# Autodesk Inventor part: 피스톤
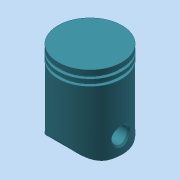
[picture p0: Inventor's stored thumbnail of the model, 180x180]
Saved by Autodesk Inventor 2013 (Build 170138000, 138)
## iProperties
Created: 2017-05
Part Number: 피스톤
Material: 알루미늄 6061
Document SubType Name: Modeling
Designer: mduedu
Density: 2.71 g/cm^3
Mass: 87.6982 g
Surface Area: 150.47 cm^2
Volume: 32.361 cm^3
Author: mduedu
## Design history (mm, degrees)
sketch "스케치1"
  geometry: L1 (0, 0)-(20, 0); L2 (20, -50)-(15, -50); L3 (15, -50)-(15, -5); L4 (15, -5)-(0, -5); L5 (0, -5)-(0, 0); L6 (20, -3)-(18, -3); L7 (18, -3)-(18, -5); L8 (18, -5)-(20, -5); L9 (20, -7)-(18, -7); L10 (18, -7)-(18, -9); L11 (18, -9)-(20, -9); L12 (20, 0)-(20, -3); L13 (20, -5)-(20, -7); L14 (20, -9)-(20, -50); L15 (0, -60)-(0, 10) reference
  constraints: 28 end point, 10 parallel, 5 perpendicular, 4 collinear, 3 horizontal
  dimensions: "d0" = 20 distance of L1.start L1.end; "d1" = 2 distance of L6.start L6.end; "d2" = 2 distance of L6.end L7.end; "d3" = 2 distance of L8.end L9.start; "d4" = 3 distance of L1.end L6.start; "d5" = 5 distance of L2.start L2.end; "d6" = 50 distance between parallel lines of L1 L2; "d7" = 5 distance of L4.end L1.start
revolve "회전1" sketch "스케치1" stored, may be unused: angle "d8" = 90 deg
fillet "모깎기1" dims "d9" = 1
sketch "스케치2"
  geometry: L1 (-50, 15)-(-50, -15) reference; C1 r 10 at (-40, 0); 1 further point
  constraints: 1 centre point, 1 horizontal alignment
  dimensions: "d10" = 20 diameter of C1; "d11" = 10 distance from line of C1.centre L1
extrude "돌출1" join sketch "스케치2" stored distance "d12" = 10; taper "d13" = 0 deg
sketch "스케치3"
  geometry: L1 (0, -20)-(-3, -20) reference; L2 (-3, -20)-(-3, -18) reference; L3 (-3, -18)-(-5, -18) reference; L4 (-5, -18)-(-5, -20) reference; L5 (-5, -20)-(-7, -20) reference; L6 (-7, -20)-(-7, -18) reference; L7 (-7, -18)-(-9, -18) reference; L8 (-9, -18)-(-9, -20) reference; L9 (-9, -20)-(-50, -20) reference; L10 (-50, -20)-(-50, -15) reference; L11 (-50, -15)-(-6, -15) reference; L12 (-5, -14)-(-5, 14) reference; L13 (-6, 15)-(-50, 15) reference; L14 (-50, 15)-(-50, 20) reference; L15 (-50, 20)-(-9, 20) reference; L16 (-9, 20)-(-9, 18) reference; L17 (-9, 18)-(-7, 18) reference; L18 (-7, 18)-(-7, 20) reference; L19 (-7, 20)-(-5, 20) reference; L20 (-5, 20)-(-5, 18) reference; L21 (-5, 18)-(-3, 18) reference; L22 (-3, 18)-(-3, 20) reference; L23 (-3, 20)-(0, 20) reference; L24 (0, 20)-(0, -20) reference; C1 r 10 at (-40, 0) reference; C2 r 5 at (-40, 0); A1 r 1 centre (-6, -14) between (-6, -15) and (-5, -14) reference; A2 r 1 centre (-6, 14) between (-5, 14) and (-6, 15) reference; 1 further point
  constraints: 1 centre point, 1 coincident
  dimensions: "d15" = 10 diameter of C2
extrude "돌출2" cut sketch "스케치3" stored distance "d16" = 10; taper "d17" = 0 deg
sketch "스케치4"
  geometry: L1 (15, -50)-(-15, -50) reference; L2 (-15, -50)-(-20, -50) reference; L3 (-20, -50)-(-20, -45) reference; L4 (20, -45)-(20, -50) reference; L5 (20, -50)-(15, -50) reference; L6 (-15, -30)-(15, -30) reference; L7 (15, -30)-(15, -6) reference; L8 (14, -5)-(-14, -5) reference; L9 (-15, -6)-(-15, -30) reference; L10 (-20, -3)-(-20, 0) reference; L11 (-20, 0)-(20, 0) reference; L12 (20, 0)-(20, -3) reference; L13 (20, -3)-(18, -3) reference; L14 (18, -3)-(18, -5) reference; L15 (18, -5)-(20, -5) reference; L16 (20, -5)-(20, -7) reference; L17 (20, -7)-(18, -7) reference; L18 (18, -7)-(18, -9) reference; L19 (18, -9)-(20, -9) reference; L20 (-20, -9)-(-18, -9) reference; L21 (-18, -9)-(-18, -7) reference; L22 (-18, -7)-(-20, -7) reference; L23 (-20, -7)-(-20, -5) reference; L24 (-20, -5)-(-18, -5) reference; L25 (-18, -5)-(-18, -3) reference; L26 (-18, -3)-(-20, -3) reference; L27 (0, 0)-(0, -50); L28 (-5.698, -50)-(-5, -30); L29 (5.698, -50)-(5, -30); L30 (-5, -30)-(5, -30); L31 (-5.698, -50)-(5.698, -50); L32 (-20, -45)-(20, -45) reference; L33 (20, -9)-(20, -35) reference; L34 (20, -35)-(-20, -35) reference; L35 (-20, -35)-(-20, -9) reference; A1 r 1 centre (14, -6) between (15, -6) and (14, -5) reference; A2 r 1 centre (-14, -6) between (-14, -5) and (-15, -6) reference
  constraints: 10 end point, 2 point on line, 2 symmetric about line, 1 midpoint, 1 parallel, 1 perpendicular
  dimensions: "d18" = 2 deg angle of L27 L28; "d19" = 5 distance from line of L27 L28.end
extrude "돌출3" cut sketch "스케치4" stored distance "d20" = 20; taper "d21" = 0 deg
chamfer "모따기1" distance "d22" = 1; stored, may be unused: second distance "d23" = 2, angle "d24" = 45 deg
sketch "스케치5"
  geometry: L1 (-50, 0)-(-50, -15) reference; L2 (-50, 15)-(-50, 0) reference; L3 (-9, 20)-(-50, 20) reference; L4 (-50, 20)-(-50, -20) reference; L5 (-9, -20)-(-50, -20) reference; L6 (-42.483, -20)-(-50, -20); L7 (-50, -20)-(-50, -7); L8 (-42.483, 20)-(-50, 20); L9 (-50, 20)-(-50, 7); A1 r 15 centre (-35, 7) between (-42.483, 20) and (-50, 7); A2 r 15 centre (-35, -7) between (-42.483, -20) and (-50, -7); 1 further point
  constraints: 8 end point, 4 point on circle, 4 point on line, 2 centre point, 2 tangent, 1 collinear, 1 equal radius, 1 perpendicular
  dimensions: "d25" = 30 diameter of A1; "d26" = 7 vertical distance of A2.centre point (0, 0); "d27" = 7 vertical distance of point (0, 0) A1.centre (= d26)
extrude "돌출4" cut sketch "스케치5" stored distance "d28" = 20; taper "d29" = 0 deg
node "솔리드1"
node "절단 모서리 투영1"
node "절단 모서리 투영2"
